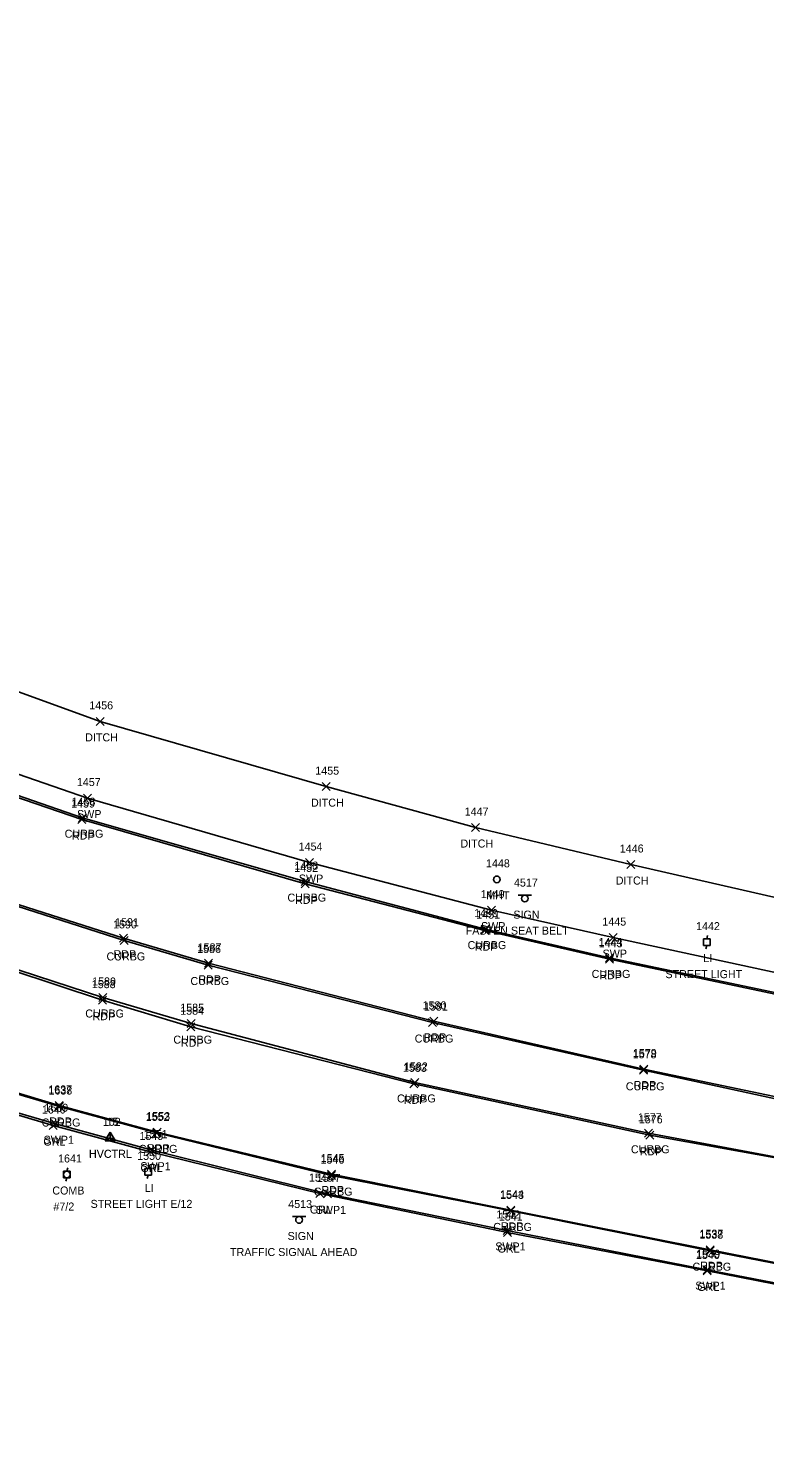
# Model space of a CAD drawing. Extents: x 1690689 to 1696275, y 438760 to 444007.
# Drawn here: x 1692264.7 to 1692448.7, y 438909.1 to 439260.7 of the extents above; entities that cross this region are included whole.
import ezdxf

# ---------------------------------------------------------------- set-up
doc = ezdxf.new("R2010")
doc.units = 0
for name, color, linetype in [('C_A', 7, 'Continuous'), ('C_I', 7, 'Continuous'), ('CPSM', 7, 'Continuous'), ('D_A', 7, 'Continuous'), ('D_I', 7, 'Continuous'), ('D_TIC', 7, 'Continuous'), ('DD', 7, 'Continuous'), ('P_A', 7, 'Continuous'), ('P_I', 7, 'Continuous'), ('P_TIC', 7, 'Continuous'), ('PET', 7, 'Continuous'), ('R_A', 7, 'Continuous'), ('R_I', 7, 'Continuous'), ('R_TIC', 7, 'Continuous'), ('RC', 7, 'Continuous'), ('RGR', 7, 'Continuous'), ('RSW', 7, 'Continuous'), ('S_A', 7, 'Continuous'), ('S_C', 7, 'Continuous'), ('S_I', 7, 'Continuous'), ('SSGN', 7, 'Continuous'), ('U_A', 7, 'Continuous'), ('U_C', 7, 'Continuous'), ('U_I', 7, 'Continuous'), ('ULP', 7, 'Continuous'), ('UP', 7, 'Continuous'), ('UTMH', 7, 'Continuous')]:
    doc.layers.add(name, color=color, linetype=linetype)

msp = doc.modelspace()

# ---------------------------------------------------------------- linework, layer by layer
at = {"layer": 'CPSM'}
for p, q in [((1692283.91, 438982.65), (1692285.16, 438984.81)), ((1692283.91, 438982.65), (1692285.16, 438983.37)), ((1692283.93, 438982.63), (1692285.18, 438984.79)), ((1692283.93, 438982.63), (1692285.18, 438983.35)), ((1692286.41, 438982.65), (1692285.16, 438984.81)), ((1692285.16, 438983.37), (1692285.16, 438984.81)), ((1692285.16, 438983.37), (1692285.16, 438983.37)), ((1692285.16, 438983.37), (1692286.41, 438982.65)), ((1692286.43, 438982.63), (1692285.18, 438984.79)), ((1692285.18, 438983.35), (1692285.18, 438984.79)), ((1692285.18, 438983.35), (1692285.18, 438983.35)), ((1692285.18, 438983.35), (1692286.43, 438982.63)), ((1692283.91, 438982.65), (1692286.41, 438982.65)), ((1692283.93, 438982.63), (1692286.43, 438982.63))]:
    msp.add_line(p, q, dxfattribs=at)
at = {"layer": 'D_TIC'}
for points in [[(1692281.68, 439086.44), (1692283.68, 439088.44)], [(1692283.68, 439086.44), (1692281.68, 439088.44)], [(1692338.07, 439070.12), (1692340.07, 439072.12)], [(1692340.07, 439070.12), (1692338.07, 439072.12)], [(1692375.4, 439059.91), (1692377.4, 439061.91)], [(1692377.4, 439059.91), (1692375.4, 439061.91)], [(1692414.19, 439050.66), (1692416.19, 439052.66)], [(1692416.19, 439050.66), (1692414.19, 439052.66)]]:
    msp.add_lwpolyline(points, dxfattribs=at)
at = {"layer": 'DD'}
msp.add_lwpolyline([(1692601.69, 439017.79), (1692563.37, 439021.21), (1692508.43, 439031.44), (1692465.47, 439040.14), (1692415.19, 439051.66), (1692376.4, 439060.91), (1692339.07, 439071.12), (1692282.68, 439087.44), (1692232.86, 439105.49), (1692192.88, 439120.62), (1692157.57, 439136.03), (1692114.74, 439157.79), (1692067.68, 439181.46), (1692012.38, 439226.11), (1692016.4, 439238.61), (1692018.77, 439248.28), (1692013.27, 439253.9), (1692009.52, 439256.4)], dxfattribs=at)
at = {"layer": 'P_TIC'}
for points in [[(1692277.1, 439061.9), (1692279.1, 439063.9)], [(1692279.1, 439061.9), (1692277.1, 439063.9)], [(1692332.82, 439045.83), (1692334.82, 439047.83)], [(1692334.82, 439045.83), (1692332.82, 439047.83)], [(1692377.72, 439034.13), (1692379.72, 439036.13)], [(1692379.72, 439034.13), (1692377.72, 439036.13)], [(1692287.49, 439032.25), (1692289.49, 439034.25)], [(1692289.49, 439032.25), (1692287.49, 439034.25)], [(1692408.86, 439026.99), (1692410.86, 439028.99)], [(1692410.86, 439026.99), (1692408.86, 439028.99)], [(1692308.7, 439025.97), (1692310.7, 439027.97)], [(1692310.7, 439025.97), (1692308.7, 439027.97)], [(1692282.25, 439016.76), (1692284.25, 439018.76)], [(1692284.25, 439016.76), (1692282.25, 439018.76)], [(1692304.33, 439010.12), (1692306.33, 439012.12)], [(1692306.33, 439010.12), (1692304.33, 439012.12)], [(1692364.96, 439011.47), (1692366.96, 439013.47)], [(1692366.96, 439011.47), (1692364.96, 439013.47)], [(1692417.41, 438999.55), (1692419.41, 439001.55)], [(1692419.41, 438999.55), (1692417.41, 439001.55)], [(1692359.97, 438995.85), (1692361.97, 438997.85)], [(1692361.97, 438995.85), (1692359.97, 438997.85)], [(1692271.43, 438990.45), (1692273.43, 438992.45)], [(1692273.43, 438990.45), (1692271.43, 438992.45)], [(1692295.87, 438983.77), (1692297.87, 438985.77)], [(1692297.87, 438983.77), (1692295.87, 438985.77)], [(1692418.94, 438982.98), (1692420.94, 438984.98)], [(1692420.94, 438982.98), (1692418.94, 438984.98)], [(1692339.43, 438973.31), (1692341.43, 438975.31)], [(1692341.43, 438973.31), (1692339.43, 438975.31)], [(1692384.23, 438964.25), (1692386.23, 438966.25)], [(1692386.23, 438964.25), (1692384.23, 438966.25)], [(1692434.03, 438954.4), (1692436.03, 438956.4)], [(1692436.03, 438954.4), (1692434.03, 438956.4)]]:
    msp.add_lwpolyline(points, dxfattribs=at)
at = {"layer": 'PET'}
for points in [[(1692506.42, 439007.58), (1692409.86, 439027.99), (1692378.72, 439035.13), (1692333.82, 439046.83), (1692278.1, 439062.9), (1692234.78, 439077.7), (1692205.8, 439088.84), (1692153.42, 439111.21), (1692107.02, 439133.53), (1692055.61, 439162.86), (1692031.29, 439179.06), (1692011.62, 439193.84), (1692002.42, 439202.85), (1692001.04, 439204.48), (1691998.47, 439209.28), (1691996.33, 439214.88), (1691994.6, 439223.82), (1691994.86, 439229.58), (1691997.14, 439239.21), (1692003.46, 439250.16), (1692011.11, 439259.34), (1692010.11, 439260.69)], [(1692765.95, 438921.86), (1692671.87, 438941.97), (1692616.75, 438954.47), (1692587.11, 438960.22), (1692543.54, 438967.18), (1692506.54, 438970.09), (1692469.43, 438975.08), (1692419.94, 438983.98), (1692360.97, 438996.85), (1692305.33, 439011.12), (1692283.25, 439017.76), (1692237.36, 439032.88), (1692203.62, 439044.85), (1692162.64, 439062.19), (1692110.81, 439085.42), (1692073.76, 439104.17), (1692029.3, 439128.96), (1692004.08, 439144.9), (1691989.31, 439154.72), (1691981.95, 439161.75), (1691978.54, 439168.17), (1691978.42, 439170.83), (1691980.54, 439171.6)], [(1692767.64, 438925.55), (1692673.48, 438945.69), (1692617.32, 438957.74), (1692543.2, 438973.83), (1692470.55, 438989.57), (1692418.41, 439000.55), (1692365.96, 439012.47), (1692309.7, 439026.97), (1692288.49, 439033.25), (1692244.35, 439047.34), (1692210.04, 439059.59), (1692168.81, 439075.98), (1692116.96, 439099.81), (1692081.46, 439117.73), (1692037.17, 439142.63), (1692008.65, 439160.43), (1691998.95, 439166.12), (1691980.54, 439171.6)], [(1692485.07, 438945.57), (1692435.03, 438955.4), (1692385.23, 438965.25), (1692340.43, 438974.31), (1692296.87, 438984.77), (1692272.43, 438991.45), (1692235.97, 439002.41), (1692197.17, 439015.62), (1692153.62, 439031.87), (1692118.48, 439046.77), (1692081.06, 439063.89), (1692043.59, 439082.96), (1692015.06, 439098.81), (1691980.04, 439119.84), (1691962.57, 439130.66), (1691955.71, 439134.26), (1691947.97, 439136.72), (1691941.75, 439137.91), (1691935.77, 439138.24), (1691931.84, 439138.11), (1691929.14, 439137.6), (1691914.86, 439134.28)]]:
    msp.add_lwpolyline(points, dxfattribs=at)
at = {"layer": 'R_TIC'}
for points in [[(1692278.52, 439067.27), (1692280.52, 439069.27)], [(1692280.52, 439067.27), (1692278.52, 439069.27)], [(1692277.2, 439062.36), (1692279.2, 439064.36)], [(1692279.2, 439062.36), (1692277.2, 439064.36)], [(1692333.91, 439051.16), (1692335.91, 439053.16)], [(1692335.91, 439051.16), (1692333.91, 439053.16)], [(1692332.85, 439046.39), (1692334.85, 439048.39)], [(1692334.85, 439046.39), (1692332.85, 439048.39)], [(1692379.42, 439039.26), (1692381.42, 439041.26)], [(1692381.42, 439039.26), (1692379.42, 439041.26)], [(1692377.84, 439034.52), (1692379.84, 439036.52)], [(1692379.84, 439034.52), (1692377.84, 439036.52)], [(1692287.66, 439031.69), (1692289.66, 439033.69)], [(1692289.66, 439031.69), (1692287.66, 439033.69)], [(1692409.78, 439032.39), (1692411.78, 439034.39)], [(1692411.78, 439032.39), (1692409.78, 439034.39)], [(1692408.83, 439027.32), (1692410.83, 439029.32)], [(1692410.83, 439027.32), (1692408.83, 439029.32)], [(1692308.62, 439025.54), (1692310.62, 439027.54)], [(1692310.62, 439025.54), (1692308.62, 439027.54)], [(1692282.35, 439017.43), (1692284.35, 439019.43)], [(1692284.35, 439017.43), (1692282.35, 439019.43)], [(1692304.35, 439010.89), (1692306.35, 439012.89)], [(1692306.35, 439010.89), (1692304.35, 439012.89)], [(1692364.64, 439011.16), (1692366.64, 439013.16)], [(1692366.64, 439011.16), (1692364.64, 439013.16)], [(1692417.35, 438999.23), (1692419.35, 439001.23)], [(1692419.35, 438999.23), (1692417.35, 439001.23)], [(1692360.22, 438996.2), (1692362.22, 438998.2)], [(1692362.22, 438996.2), (1692360.22, 438998.2)], [(1692271.47, 438990.18), (1692273.47, 438992.18)], [(1692273.47, 438990.18), (1692271.47, 438992.18)], [(1692269.91, 438985.42), (1692271.91, 438987.42)], [(1692271.91, 438985.42), (1692269.91, 438987.42)], [(1692270.48, 438985.87), (1692272.48, 438987.87)], [(1692272.48, 438985.87), (1692270.48, 438987.87)], [(1692295.71, 438983.59), (1692297.71, 438985.59)], [(1692297.71, 438983.59), (1692295.71, 438985.59)], [(1692418.64, 438983.49), (1692420.64, 438985.49)], [(1692420.64, 438983.49), (1692418.64, 438985.49)], [(1692294.18, 438978.82), (1692296.18, 438980.82)], [(1692296.18, 438978.82), (1692294.18, 438980.82)], [(1692294.64, 438979.27), (1692296.64, 438981.27)], [(1692296.64, 438979.27), (1692294.64, 438981.27)], [(1692339.44, 438972.91), (1692341.44, 438974.91)], [(1692341.44, 438972.91), (1692339.44, 438974.91)], [(1692336.49, 438968.42), (1692338.49, 438970.42)], [(1692338.49, 438968.42), (1692336.49, 438970.42)], [(1692338.45, 438968.35), (1692340.45, 438970.35)], [(1692340.45, 438968.35), (1692338.45, 438970.35)], [(1692384.25, 438964.09), (1692386.25, 438966.09)], [(1692386.25, 438964.09), (1692384.25, 438966.09)], [(1692383.3, 438959.21), (1692385.3, 438961.21)], [(1692385.3, 438959.21), (1692383.3, 438961.21)], [(1692383.35, 438958.68), (1692385.35, 438960.68)], [(1692385.35, 438958.68), (1692383.35, 438960.68)], [(1692434.02, 438954.15), (1692436.02, 438956.15)], [(1692436.02, 438954.15), (1692434.02, 438956.15)], [(1692433.26, 438949.4), (1692435.26, 438951.4)], [(1692435.26, 438949.4), (1692433.26, 438951.4)], [(1692433.24, 438949.09), (1692435.24, 438951.09)], [(1692435.24, 438949.09), (1692433.24, 438951.09)]]:
    msp.add_lwpolyline(points, dxfattribs=at)
at = {"layer": 'RC'}
for points in [[(1692458.66, 439018.07), (1692409.83, 439028.32), (1692378.84, 439035.52), (1692333.85, 439047.39), (1692278.2, 439063.36), (1692234.93, 439078.32), (1692206.05, 439089.01), (1692153.68, 439111.65), (1692107.21, 439133.95), (1692055.41, 439163.27), (1692031.04, 439179.71), (1692011.71, 439194.03), (1692002.37, 439202.91), (1692001.39, 439204.32), (1691998.83, 439209.21), (1691996.61, 439215.03), (1691994.98, 439223.75), (1691995.26, 439229.27), (1691997.49, 439239.08), (1692003.79, 439249.87), (1692007.64, 439254.1)], [(1692766.36, 438922.45), (1692671.96, 438942.46), (1692616.73, 438954.89), (1692587.1, 438960.64), (1692543.8, 438967.52), (1692506.49, 438970.64), (1692469.42, 438975.23), (1692419.64, 438984.49), (1692361.22, 438997.2), (1692305.35, 439011.89), (1692283.35, 439018.43), (1692237.58, 439033.34), (1692203.77, 439045.28), (1692162.83, 439062.74), (1692110.99, 439085.87), (1692073.96, 439104.65), (1692029.68, 439129.43), (1692004.27, 439145.41), (1691989.92, 439155.3), (1691982.48, 439162.24), (1691979.04, 439168.18), (1691978.75, 439170.84), (1691980.34, 439171.05)], [(1692767.42, 438924.95), (1692673.21, 438945.2), (1692617.12, 438957.34), (1692543.19, 438973.28), (1692470.51, 438988.93), (1692418.35, 439000.23), (1692365.64, 439012.16), (1692309.62, 439026.54), (1692288.66, 439032.69), (1692244.17, 439046.9), (1692209.98, 439058.96), (1692168.78, 439075.61), (1692116.61, 439099.03), (1692081.37, 439117.41), (1692037.02, 439142.1), (1692008.48, 439159.75), (1691998.71, 439165.65), (1691980.34, 439171.05)], [(1692485.06, 438945.4), (1692435.02, 438955.15), (1692385.25, 438965.09), (1692340.44, 438973.91), (1692296.71, 438984.59), (1692272.47, 438991.18), (1692235.74, 439001.99), (1692196.89, 439015.24), (1692153.55, 439031.62), (1692118.26, 439046.46), (1692080.62, 439063.88)]]:
    msp.add_lwpolyline(points, dxfattribs=at)
at = {"layer": 'RGR'}
msp.add_lwpolyline([(1692484.4, 438940.25), (1692434.24, 438950.09), (1692384.35, 438959.68), (1692337.49, 438969.42), (1692295.18, 438979.82), (1692270.91, 438986.42), (1692234.48, 438997.25), (1692193.82, 439010.96), (1692152.08, 439026.6), (1692115.78, 439041.61), (1692078.11, 439058.76)], dxfattribs=at)
at = {"layer": 'RSW'}
for points in [[(1692665.59, 438979.47), (1692633.47, 438986.11), (1692606.01, 438992.31), (1692555.68, 439002.49), (1692507.66, 439012.62), (1692459.75, 439022.83), (1692410.78, 439033.39), (1692380.42, 439040.26), (1692334.91, 439052.16), (1692279.52, 439068.27), (1692236.35, 439083.17), (1692207.73, 439093.85), (1692155.83, 439116.19), (1692109.79, 439138.3), (1692057.98, 439167.75), (1692033.9, 439183.79), (1692014.53, 439197.98), (1692008.04, 439204.8), (1692006.24, 439207.82), (1692001.39, 439204.32)], [(1692637.9, 438909.12), (1692604.66, 438916.25), (1692559.9, 438925.87), (1692526.71, 438932.34), (1692484.3, 438940.72), (1692434.26, 438950.4), (1692384.3, 438960.21), (1692339.45, 438969.35), (1692295.64, 438980.27), (1692271.48, 438986.87), (1692234.38, 438997.66), (1692195.38, 439010.77), (1692151.68, 439027.12), (1692116.08, 439041.96), (1692078.43, 439059.23), (1692041.02, 439078.87), (1692012.59, 439094.44), (1691977.25, 439115.7), (1691958.72, 439127.11), (1691952.86, 439130.25), (1691946.68, 439131.94), (1691948, 439136.19)]]:
    msp.add_lwpolyline(points, dxfattribs=at)
at = {"layer": 'SSGN'}
for p, q in [((1692387.07, 439043.99), (1692390.41, 439043.99)), ((1692388.72, 439043.16), (1692388.72, 439043.16)), ((1692330.69, 438963.66), (1692334.02, 438963.66)), ((1692332.33, 438962.83), (1692332.33, 438962.83))]:
    msp.add_line(p, q, dxfattribs=at)
for centre in [(1692388.72, 439043.16), (1692332.33, 438962.83)]:
    msp.add_circle(centre, 0.833, dxfattribs=at)
at = {"layer": 'ULP'}
for p, q in [((1692433.35, 439031.43), (1692433.35, 439033.09)), ((1692433.35, 439033.09), (1692435.02, 439033.09)), ((1692434.35, 439033.93), (1692434.19, 439033.09)), ((1692434.19, 439032.26), (1692434.19, 439032.26)), ((1692435.02, 439033.09), (1692435.02, 439031.43)), ((1692435.02, 439031.43), (1692433.35, 439031.43)), ((1692433.94, 439030.59), (1692434.19, 439031.43)), ((1692294.84, 438976.52), (1692294.67, 438975.69)), ((1692293.84, 438974.02), (1692293.84, 438975.69)), ((1692293.84, 438975.69), (1692295.51, 438975.69)), ((1692295.51, 438974.02), (1692293.84, 438974.02)), ((1692294.42, 438973.19), (1692294.67, 438974.02)), ((1692294.67, 438974.85), (1692294.67, 438974.85)), ((1692295.51, 438975.69), (1692295.51, 438974.02))]:
    msp.add_line(p, q, dxfattribs=at)
at = {"layer": 'UP'}
for p, q in [((1692274.57, 438975.86), (1692274.32, 438975.02)), ((1692273.48, 438973.36), (1692273.48, 438975.02)), ((1692273.48, 438975.02), (1692275.15, 438975.02)), ((1692275.15, 438973.36), (1692273.48, 438973.36)), ((1692274.07, 438972.52), (1692274.32, 438973.36)), ((1692274.32, 438974.19), (1692274.32, 438974.19)), ((1692275.15, 438975.02), (1692275.15, 438973.36))]:
    msp.add_line(p, q, dxfattribs=at)
msp.add_circle((1692274.32, 438974.19), 0.833, dxfattribs=at)
at = {"layer": 'UTMH'}
for p, q in [((1692381.71, 439047.95), (1692381.71, 439047.95)), ((1692382.54, 439047.95), (1692382.54, 439047.95))]:
    msp.add_line(p, q, dxfattribs=at)
msp.add_circle((1692381.71, 439047.95), 0.833, dxfattribs=at)

# ---------------------------------------------------------------- texts
at = {"layer": 'C_A'}
for p in [(1692279.85, 438978.37), (1692279.88, 438978.35)]:
    msp.add_text('HVCTRL', height=2, dxfattribs=at).set_placement(p)
at = {"layer": 'C_I'}
for s, p in [('102', (1692283.31, 438986.35)), ('15', (1692284.26, 438986.37))]:
    msp.add_text(s, height=2, dxfattribs=at).set_placement(p)
at = {"layer": 'D_A'}
for p in [(1692278.91, 439082.44), (1692335.31, 439066.12), (1692372.63, 439055.91), (1692411.43, 439046.66)]:
    msp.add_text('DITCH', height=2, dxfattribs=at).set_placement(p)
at = {"layer": 'D_I'}
for s, p in [('1456', (1692279.93, 439090.44)), ('1455', (1692336.38, 439074.12)), ('1447', (1692373.7, 439063.91)), ('1446', (1692412.44, 439054.66))]:
    msp.add_text(s, height=2, dxfattribs=at).set_placement(p)
at = {"layer": 'P_A'}
for p in [(1692275.59, 439057.9), (1692331.31, 439041.83), (1692376.21, 439030.13), (1692285.98, 439028.25), (1692407.35, 439022.99), (1692307.18, 439021.97), (1692280.74, 439012.76), (1692302.82, 439006.12), (1692363.45, 439007.47), (1692415.9, 438995.55), (1692358.45, 438991.85), (1692269.92, 438986.45), (1692294.36, 438979.77), (1692417.43, 438978.98), (1692337.92, 438969.31), (1692382.72, 438960.25), (1692432.52, 438950.4)]:
    msp.add_text('RDP', height=2, dxfattribs=at).set_placement(p)
at = {"layer": 'P_I'}
for s, p in [('1459', (1692275.4, 439065.9)), ('1452', (1692331.13, 439049.83)), ('1451', (1692376.59, 439038.13)), ('1591', (1692286.37, 439036.25)), ('1443', (1692407.17, 439030.99)), ('1587', (1692307, 439029.97)), ('1588', (1692280.56, 439020.76)), ('1584', (1692302.64, 439014.12)), ('1580', (1692363.18, 439015.47)), ('1579', (1692415.71, 439003.55)), ('1583', (1692358.27, 438999.85)), ('1637', (1692269.69, 438994.45)), ('1553', (1692294.17, 438987.77)), ('1576', (1692417.19, 438986.98)), ('1545', (1692337.74, 438977.31)), ('1544', (1692382.54, 438968.25)), ('1537', (1692432.34, 438958.4))]:
    msp.add_text(s, height=2, dxfattribs=at).set_placement(p)
at = {"layer": 'R_A'}
for s, p in [('SWP', (1692276.88, 439063.27)), ('CURBG', (1692273.78, 439058.36)), ('SWP', (1692332.27, 439047.16)), ('CURBG', (1692329.43, 439042.39)), ('SWP', (1692377.78, 439035.26)), ('CURBG', (1692374.43, 439030.52)), ('CURBG', (1692284.24, 439027.69)), ('SWP', (1692408.14, 439028.39)), ('CURBG', (1692405.41, 439023.32)), ('CURBG', (1692305.2, 439021.54)), ('CURBG', (1692278.93, 439013.43)), ('CURBG', (1692300.93, 439006.89)), ('CURBG', (1692361.22, 439007.16)), ('CURBG', (1692413.94, 438995.23)), ('CURBG', (1692356.8, 438992.2)), ('CURBG', (1692268.05, 438986.18)), ('GRL', (1692268.45, 438981.42)), ('SWP1', (1692268.52, 438981.87)), ('CURBG', (1692292.29, 438979.59)), ('CURBG', (1692415.22, 438979.49)), ('SWP1', (1692292.68, 438975.27)), ('GRL', (1692292.73, 438974.82)), ('CURBG', (1692336.02, 438968.91)), ('GRL', (1692335.03, 438964.42)), ('SWP1', (1692336.49, 438964.35)), ('CURBG', (1692380.83, 438960.09)), ('SWP1', (1692381.34, 438955.21)), ('GRL', (1692381.9, 438954.68)), ('CURBG', (1692430.6, 438950.15)), ('SWP1', (1692431.3, 438945.4)), ('GRL', (1692431.79, 438945.09))]:
    msp.add_text(s, height=2, dxfattribs=at).set_placement(p)
at = {"layer": 'R_I'}
for s, p in [('1457', (1692276.83, 439071.27)), ('1458', (1692275.5, 439066.36)), ('1454', (1692332.22, 439055.16)), ('1453', (1692331.16, 439050.39)), ('1449', (1692377.72, 439043.26)), ('1450', (1692376.06, 439038.52)), ('1590', (1692285.88, 439035.69)), ('1445', (1692408.08, 439036.39)), ('1444', (1692407.14, 439031.32)), ('1586', (1692306.87, 439029.54)), ('1589', (1692280.65, 439021.43)), ('1585', (1692302.66, 439014.89)), ('1581', (1692363.51, 439015.16)), ('1578', (1692415.66, 439003.23)), ('1582', (1692358.53, 439000.2)), ('1638', (1692269.73, 438994.18)), ('1640', (1692268.08, 438989.42)), ('1639', (1692268.73, 438989.87)), ('1552', (1692294.02, 438987.59)), ('1577', (1692416.94, 438987.49)), ('1549', (1692292.48, 438982.82)), ('1551', (1692293.52, 438983.27)), ('1546', (1692337.69, 438976.91)), ('1548', (1692334.8, 438972.42)), ('1547', (1692336.76, 438972.35)), ('1543', (1692382.55, 438968.09)), ('1542', (1692381.6, 438963.21)), ('1541', (1692382.23, 438962.68)), ('1538', (1692432.32, 438958.15)), ('1540', (1692431.46, 438953.09)), ('1539', (1692431.56, 438953.4))]:
    msp.add_text(s, height=2, dxfattribs=at).set_placement(p)
at = {"layer": 'S_A'}
for p in [(1692385.86, 439038.14), (1692329.47, 438957.81)]:
    msp.add_text('SIGN', height=2, dxfattribs=at).set_placement(p)
at = {"layer": 'S_C'}
for s, p in [('FASTEN SEAT BELT', (1692373.95, 439034.14)), ('TRAFFIC SIGNAL AHEAD', (1692315.09, 438953.81))]:
    msp.add_text(s, height=2, dxfattribs=at).set_placement(p)
at = {"layer": 'S_I'}
for s, p in [('4517', (1692386.01, 439046.14)), ('4513', (1692329.62, 438965.81))]:
    msp.add_text(s, height=2, dxfattribs=at).set_placement(p)
at = {"layer": 'U_A'}
for s, p in [('MHT', (1692379.09, 439042.95)), ('LI', (1692433.29, 439027.26)), ('COMB', (1692270.7, 438969.19)), ('LI', (1692293.78, 438969.85))]:
    msp.add_text(s, height=2, dxfattribs=at).set_placement(p)
at = {"layer": 'U_C'}
for s, p in [('STREET LIGHT', (1692423.85, 439023.26)), ('#7/2', (1692270.98, 438965.19)), ('STREET LIGHT E/12', (1692280.26, 438965.85))]:
    msp.add_text(s, height=2, dxfattribs=at).set_placement(p)
at = {"layer": 'U_I'}
for s, p in [('1448', (1692379.02, 439050.95)), ('1442', (1692431.49, 439035.26)), ('1550', (1692291.89, 438977.85)), ('1641', (1692272.14, 438977.19))]:
    msp.add_text(s, height=2, dxfattribs=at).set_placement(p)

doc.saveas('drawing.dxf')
